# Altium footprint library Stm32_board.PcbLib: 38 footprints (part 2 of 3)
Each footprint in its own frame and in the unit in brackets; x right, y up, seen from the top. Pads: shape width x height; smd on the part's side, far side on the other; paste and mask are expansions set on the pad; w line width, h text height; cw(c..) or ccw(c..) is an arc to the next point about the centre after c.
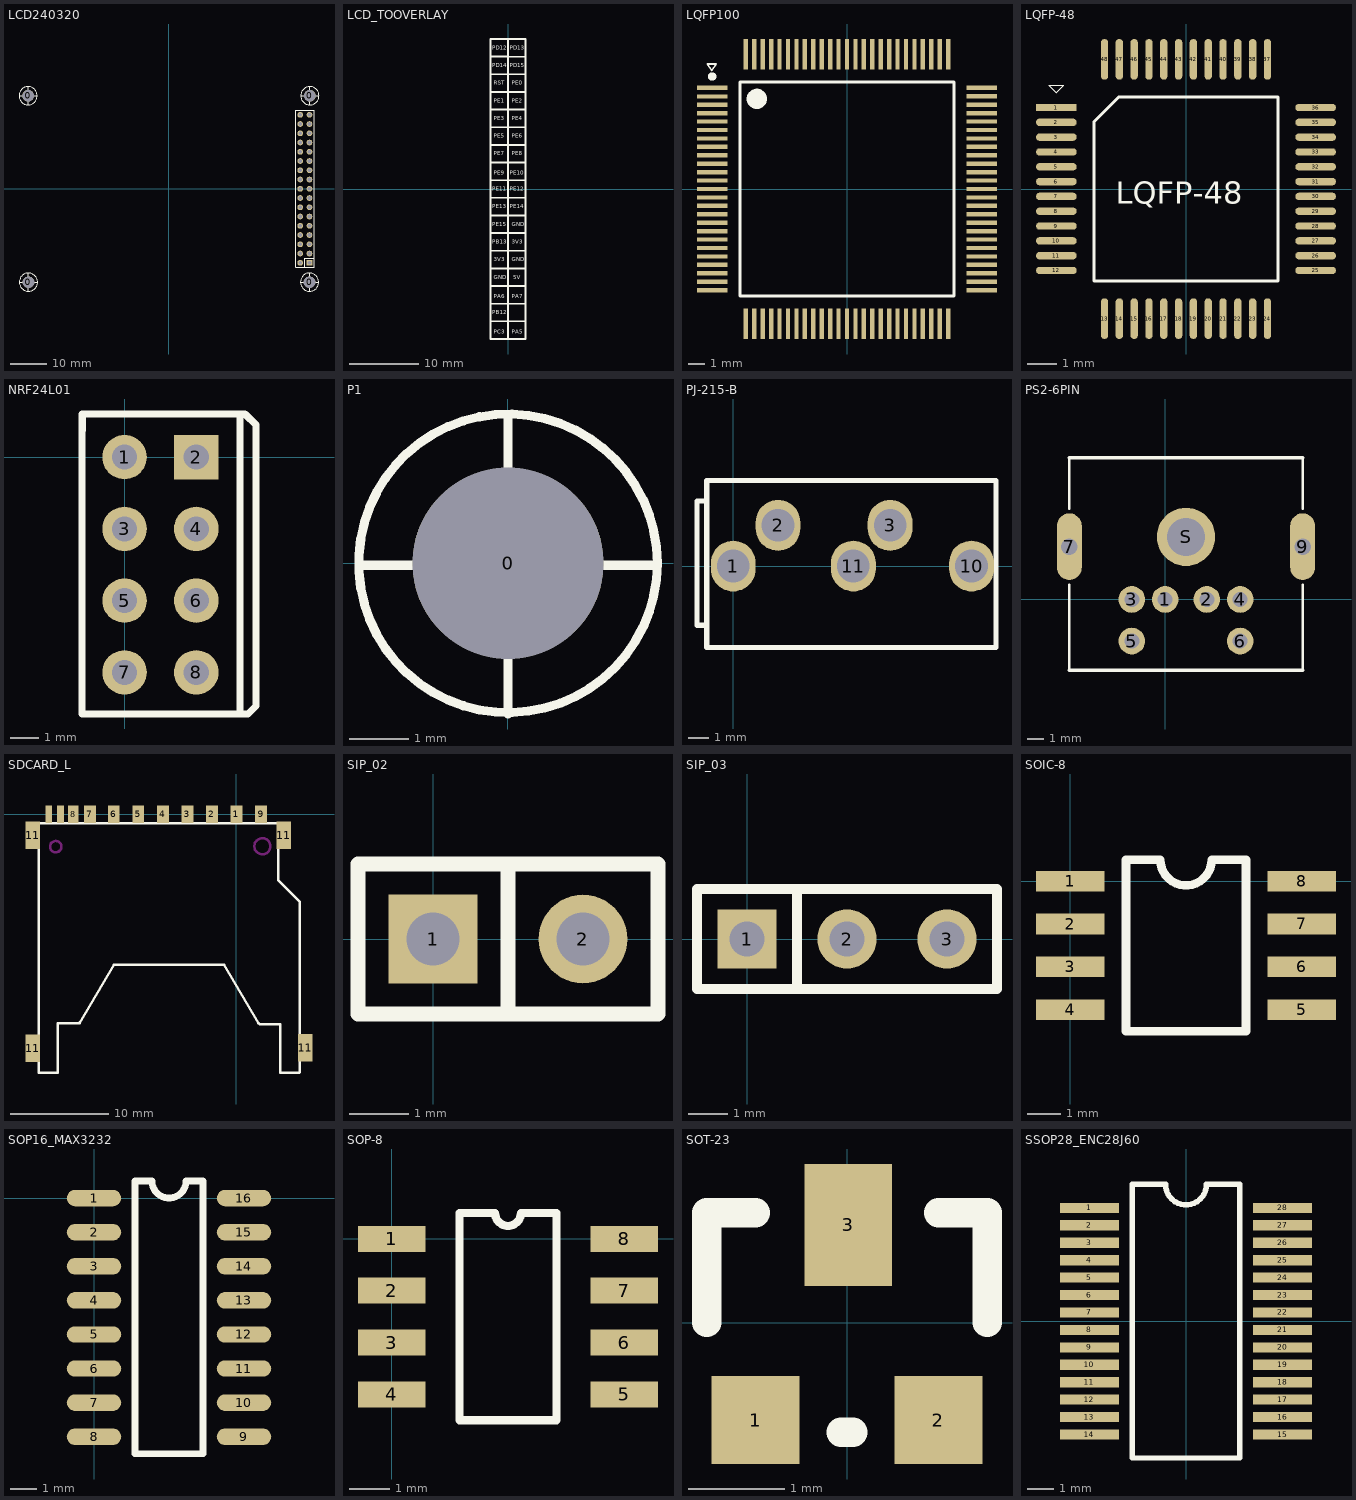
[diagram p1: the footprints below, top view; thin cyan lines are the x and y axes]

## LCD240320 [mil]
pads (38):
  round 125.98 hole 125.98 unplated: 0(-1523.62,1007.87) 0(-1519.68,-1007.87) 0(1519.69,-1007.87) 0(1523.62,1007.87)
  rect 62x62 hole 40: 1(1518.66,-798.27)
  round 62 hole 40: 2(1418.66,-798.27) 3(1518.66,-698.27) 4(1418.66,-698.27) 5(1518.66,-598.27) 6(1418.66,-598.27) 7(1518.66,-498.27) 8(1418.66,-498.27) 9(1518.66,-398.27) 10(1418.66,-398.27) 11(1518.66,-298.27) 12(1418.66,-298.27) 13(1518.66,-198.27) 14(1418.66,-198.27) 15(1518.66,-98.27) 16(1418.66,-98.27) 17(1518.66,1.73) 18(1418.66,1.73) 19(1518.66,101.73) 20(1418.66,101.73) 21(1518.66,201.73) 22(1418.66,201.73) 23(1518.66,301.73) 24(1418.66,301.73) 25(1518.66,401.73) 26(1418.66,401.73) 27(1518.66,501.73) 28(1418.66,501.73) 29(1518.66,601.73) 30(1418.66,601.73) 31(1518.66,701.73) 32(1418.66,701.73) 33(1518.66,801.73) 34(1418.66,801.73)
Top Overlay:
  circle w6: c1519.69,-1007.87 r98.43
  circle w6: c1523.62,1007.87 r98.43
  circle w6: c-1519.68,-1007.87 r98.43
  circle w6: c-1523.62,1007.87 r98.43
  lines w6: -1621.68,1006.59 -1426.48,1006.59 ; -1617.75,-1009.16 -1422.54,-1009.16 ; -1523.62,908.53 -1523.62,1007.87 -1523.62,1104.65 ; -1519.68,-1107.22 -1519.68,-1007.87 -1519.68,-911.09 ; 1421.62,-1009.16 1616.83,-1009.16 ; 1425.56,1006.59 1620.76,1006.59 ; 1519.69,-1107.22 1519.69,-1007.87 1519.69,-911.09 ; 1523.62,908.53 1523.62,1007.87 1523.62,1104.65
  lines w12: 1468.66,-848.27 1468.66,-748.27 1568.66,-748.27 ; 1368.66,-848.27 1368.66,851.73 1568.66,851.73 1568.66,-848.27 1368.66,-848.27

## LCD_TOOVERLAY [mil]
Top Overlay:
  lines w10: -100,-750 100,-750 ; -100,-650 100,-650 ; -100,-550 100,-550 ; -100,-450 100,-450 ; -100,-350 100,-350 ; -100,-250 100,-250 ; -100,-150 100,-150 ; -100,-50 100,-50 ; -100,50 100,50 ; -100,150 100,150 ; -100,250 100,250 ; -100,350 100,350 ; -100,450 100,450 ; -100,550 100,550 ; -100,650 100,650 ; -20,750 100,750 ; 0,-850 0,850 ; 100,750 100,750
  lines w12: -100,750 0,750 0,850 ; -100,-850 -100,850 100,850 100,-850 -100,-850
  text "PA5" at 20,-820 h22
  text "PC3" at -80,-820 h22
  text "PB12" at -90,-710 h22
  text "PA7" at 20,-620 h22
  text "PA6" at -80,-620 h22
  text "5V" at 30,-510 h22
  text "GND" at -80,-510 h22
  text "PE15" at -90,-210 h22
  text "PE14" at 10,-110 h22
  text "PE13" at -90,-110 h22
  text "PE12" at 10,-10 h22
  text "PE11" at -90,-10 h22
  text "PE10" at 10,80 h22
  text "PE9" at -80,80 h22
  text "PE8" at 20,190 h22
  text "PE7" at -80,190 h22
  text "PE6" at 20,290 h22
  text "PE5" at -80,290 h22
  text "PE4" at 20,390 h22
  text "PE3" at -80,390 h22
  text "PE2" at 20,490 h22
  text "PE1" at -80,490 h22
  text "PE0" at 20,590 h22
  text "RST" at -80,590 h22
  text "PD15" at 10,690 h22
  text "PD14" at -90,690 h22
  text "PD13" at 10,790 h22
  text "PD12" at -90,790 h22
  text "GND" at 20,-210 h22
  text "PB13" at -90,-310 h22
  text "3V3" at 20,-310 h22
  text "3V3" at -80,-410 h22
  text "GND" at 20,-410 h22

## LQFP100 [mm]
pads (100):
  rect 1.8x0.254 smd: 1(-8,6) 2(-8,5.492) 3(-8,5) 4(-8,4.5) 5(-8,4) 6(-8,3.5) 7(-8,3) 8(-8,2.5) 9(-8,2) 10(-8,1.5) 11(-8,1) 12(-8,0.5) 13(-8,0) 14(-8,-0.5) 15(-8,-1) 16(-8,-1.5) 17(-8,-2) 18(-8,-2.5) 19(-8,-3) 20(-8,-3.5) 21(-8,-4) 22(-8,-4.5) 23(-8,-5) 24(-8,-5.5) 25(-8,-6) 51(8,-6) 52(8,-5.5) 53(8,-5) 54(8,-4.5) 55(8,-4) 56(8,-3.5) 57(8,-3) 58(8,-2.5) 59(8,-2) 60(8,-1.5) 61(8,-1) 62(8,-0.5) 63(8,0) 64(8,0.5) 65(8,1) 66(8,1.5) 67(8,2) 68(8,2.5) 69(8,3) 70(8,3.5) 71(8,4) 72(8,4.5) 73(8,5) 74(8,5.5) 75(8,6)
  rect 0.254x1.8 smd: 26(-6,-8) 27(-5.5,-8) 28(-5,-8) 29(-4.5,-8) 30(-4,-8) 31(-3.5,-8) 32(-3,-8) 33(-2.5,-8) 34(-2,-8) 35(-1.5,-8) 36(-1,-8) 37(-0.5,-8) 38(0,-8) 39(0.5,-8) 40(1,-8) 41(1.5,-8) 42(2,-8) 43(2.5,-8) 44(3,-8) 45(3.5,-8) 46(4,-8) 47(4.5,-8) 48(5,-8) 49(5.5,-8) 50(6,-8) 76(6,8) 77(5.5,8) 78(5,8) 79(4.5,8) 80(4,8) 81(3.5,8) 82(3,8) 83(2.5,8) 84(2,8) 85(1.5,8) 86(1,8) 87(0.5,8) 88(0,8) 89(-0.5,8) 90(-1,8) 91(-1.5,8) 92(-2,8) 93(-2.5,8) 94(-3,8) 95(-3.5,8) 96(-4,8) 97(-4.5,8) 98(-5,8) 99(-5.5,8) 100(-6,8)
Top Overlay:
  circle w0.6: c-5.35,5.35 r0.3
  circle w0.25: c-8,6.675 r0.125
  lines w0.102: -8.28,7.417 -7.772,7.417 -8.026,7.036 -8.28,7.417
  lines w0.2: -6.35,-6.35 6.35,-6.35 6.35,6.35 -6.35,6.35 -6.35,-6.35

## LQFP-48 [mil]
pads (48):
  rect 55x10 smd: 1(-175,110)
  oval 55x10 smd: 2(-175,90) 3(-175,70) 4(-175,50) 5(-175,30) 6(-175,10) 7(-175,-10) 8(-175,-30) 9(-175,-50) 10(-175,-70) 11(-175,-90) 12(-175,-110) 25(175,-110) 26(175,-90) 27(175,-70) 28(175,-50) 29(175,-30) 30(175,-10) 31(175,10) 32(175,30) 33(175,50) 34(175,70) 35(175,90) 36(175,110)
  oval 10x55 smd: 13(-110,-175) 14(-90,-175) 15(-70,-175) 16(-50,-175) 17(-30,-175) 18(-10,-175) 19(10,-175) 20(30,-175) 21(50,-175) 22(70,-175) 23(90,-175) 24(110,-175) 37(110,175) 38(90,175) 39(70,175) 40(50,175) 41(30,175) 42(10,175) 43(-10,175) 44(-30,175) 45(-50,175) 46(-70,175) 47(-90,175) 48(-110,175)
Top Overlay:
  lines w1: -185,140 -165,140 -175,130 -185,140
  lines w4: -124.5,-124.5 124.5,-124.5 124.5,124.5 -74,124.5 -90.5,124.5 -124.5,90.5 -124.5,74 -124.5,-124.5
  text "LQFP-48" at -95,-20 h30

## NRF24L01 [mil]
pads (8):
  round 62 hole 35: 1(0,0) 3(0,-100) 4(100,-100) 5(0,-200) 6(100,-200) 7(0,-300) 8(100,-300)
  rect 62x62 hole 35: 2(100,0)
Top Overlay:
  lines w10: 152,60 168,60 168.94,59.06 183,45 183,-347 172,-358 162,-358 ; 162,-358 -59.06,-358 -59.06,36.94 -59,37 -59,60 160.06,60 161,59.06 161,-357 162,-358

## P1 [mm]
pads (1):
  round 3.2 hole 3.2 unplated: 0(0,0)
Top Overlay:
  circle w0.152: c0,0 r2.5
  lines w0.152: -2.491,-0.033 2.467,-0.033 ; 0,-2.523 0,0 0,2.458

## PJ-215-B [mm]
pads (5):
  oval 2.2x2.5 hole 1.6: 1(0,0) 2(2.2,2) 3(7.7,2) 10(11.7,0) 11(5.9,0)
Top Overlay:
  lines w0.254: -1.3,-2.921 -1.778,-2.921 ; -1.3,-2.896 -1.753,-2.896 -1.778,-2.921 ; -1.3,3.2 -1.778,3.2 -1.778,-2.921 ; -1.3,-4 -1.3,4.2 12.9,4.2 12.9,-4 -1.3,-4

## PS2-6PIN [mm]
pads (9):
  round 1.6 hole 0.9: 1(0,0) 2(2.5,0) 3(-2,0) 4(4.5,0) 5(-2,-2.5) 6(4.5,-2.5)
  oval 1.5x4 hole 1: 7(-5.75,3.166) 9(8.25,3.166)
  round 3.5 hole 2.3: S(1.25,3.75)
Top Overlay:
  lines w0.152: -5.75,-4.25 -5.75,0.88 ; -5.75,5.452 -5.75,8.5 ; 8.25,-4.25 8.25,0.88 ; 8.25,5.452 8.25,8.5
  lines w0.2: -5.75,-4.25 8.25,-4.25 ; -5.75,8.5 8.25,8.5

## SDCARD_L [mm]
pads (15):
  rect 1.2x1.8 smd: 1(0,0) 2(-2.489,0) 3(-4.983,-0.009) 4(-7.483,-0.009) 5(-9.983,-0.009) 6(-12.483,-0.009) 7(-14.908,-0.009) 9(2.517,-0.009)
  rect 1.1x1.8 smd: 8(-16.612,0)
  rect 0.7x1.8 smd: 10(-17.908,-0.009) 12(-19.101,0)
  rect 1.5x2.8 smd: 11(-20.726,-23.834) 11(-20.726,-2.143) 11(4.826,-2.143) 11(7.01,-23.784)
Top Overlay:
  lines w0.254: -18.158,-21.3 -18.158,-26.3 -20.131,-26.3 -20.131,-0.914 -20.117,-0.9 4.242,-0.9 4.242,-6.71 6.431,-8.899 6.442,-8.899 6.442,-26.273 6.415,-26.3 4.442,-26.3 4.442,-21.402 2.4,-21.402 2.242,-21.244 ; -18.107,-21.294 -16.065,-21.294 -15.907,-21.136 ; -15.958,-21.294 -12.446,-15.3 ; -12.458,-15.3 -1.258,-15.3 2.242,-21.294
Keep-Out Layer:
  circle w0.254: c-18.39,-3.3 r0.58
  circle w0.254: c2.642,-3.26 r0.82

## SIP_02 [mm]
pads (2):
  rect 1.5x1.5 hole 0.9: 1(0,0)
  round 1.5 hole 0.9: 2(2.54,0)
Top Overlay:
  lines w0.254: 1.27,-1.27 1.27,1.27 ; -1.27,-1.27 3.81,-1.27 3.81,1.27 -1.27,1.27 -1.27,-1.27

## SIP_03 [mm]
pads (3):
  rect 1.5x1.5 hole 0.9: 1(0,0)
  round 1.5 hole 0.9: 2(2.54,0) 3(5.08,0)
Top Overlay:
  lines w0.254: 1.27,-1.27 1.27,1.27 ; -1.27,-1.27 -1.27,1.27 6.35,1.27 6.35,-1.27 -1.27,-1.27

## SOIC-8 [mil]
pads (8):
  rect 80x24 smd: 1(0,0) 2(0,-50.06) 3(0,-100.06) 4(0,-150.06) 5(270,-150) 6(270,-100) 7(270,-50) 8(270,0)
Top Overlay:
  lines w10: 75,24.94 75.06,25 105,25 ccw(c135,25) 165,25 204.94,25 205,24.94 205,-175.06 65,-175.06 65,24.94 95,24.94

## SOP16_MAX3232 [mil]
pads (16):
  oval 80x24 smd: 1(0,0) 2(0,-50) 3(0,-100) 4(0,-150) 5(0,-200) 6(0,-250) 7(0,-300) 8(0,-350) 9(220,-350) 10(220,-300) 11(220,-250) 12(220,-200) 13(220,-150) 14(220,-100) 15(220,-50) 16(220,0)
Top Overlay:
  lines w10: 60,-375 60,25 85,25 ccw(c110,25) 135,25 160,25 160,-375 60,-375

## SOP-8 [mil]
pads (8):
  rect 65x25 smd: 1(0,0) 2(0,-50) 3(0,-100) 4(0,-150) 5(224.41,-150) 6(224.41,-100) 7(224.41,-50) 8(224.41,0)
Top Overlay:
  lines w7.87: 65.37,-175 65.37,25 99.7,25 ccw(c112.2,25) 124.7,25 159.04,25 159.04,-175 65.37,-175

## SOT-23 [mil]
pads (3):
  rect 36x36 smd: 1(-37.5,-40) 2(37.5,-40)
  rect 36x50 smd: 3(0.5,40)
Top Overlay:
  lines w12: -57.5,0 -57.5,45 -37.5,45 ; -2.5,-45 2.5,-45 ; 37.5,45 57.5,45 57.5,0

## SSOP28_ENC28J60 [mm]
pads (28):
  rect 2.2x0.38 smd: 1(-3.6,4.225) 2(-3.6,3.575) 3(-3.6,2.925) 4(-3.6,2.275) 5(-3.6,1.625) 6(-3.6,0.975) 7(-3.6,0.325) 8(-3.6,-0.325) 9(-3.6,-0.975) 10(-3.6,-1.625) 11(-3.6,-2.275) 12(-3.6,-2.925) 13(-3.6,-3.575) 14(-3.6,-4.225) 15(3.6,-4.225) 16(3.6,-3.575) 17(3.6,-2.925) 18(3.6,-2.275) 19(3.6,-1.625) 20(3.6,-0.975) 21(3.6,-0.325) 22(3.6,0.325) 23(3.6,0.975) 24(3.6,1.625) 25(3.6,2.275) 26(3.6,2.925) 27(3.6,3.575) 28(3.6,4.225)
Top Overlay:
  lines w0.2: -2,5.1 -2,-5.1 2,-5.1 2,5.1
  lines w0.203: -2,5.1 -0.762,5.1 ccw(c0,5.1) 0.762,5.1 2,5.1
